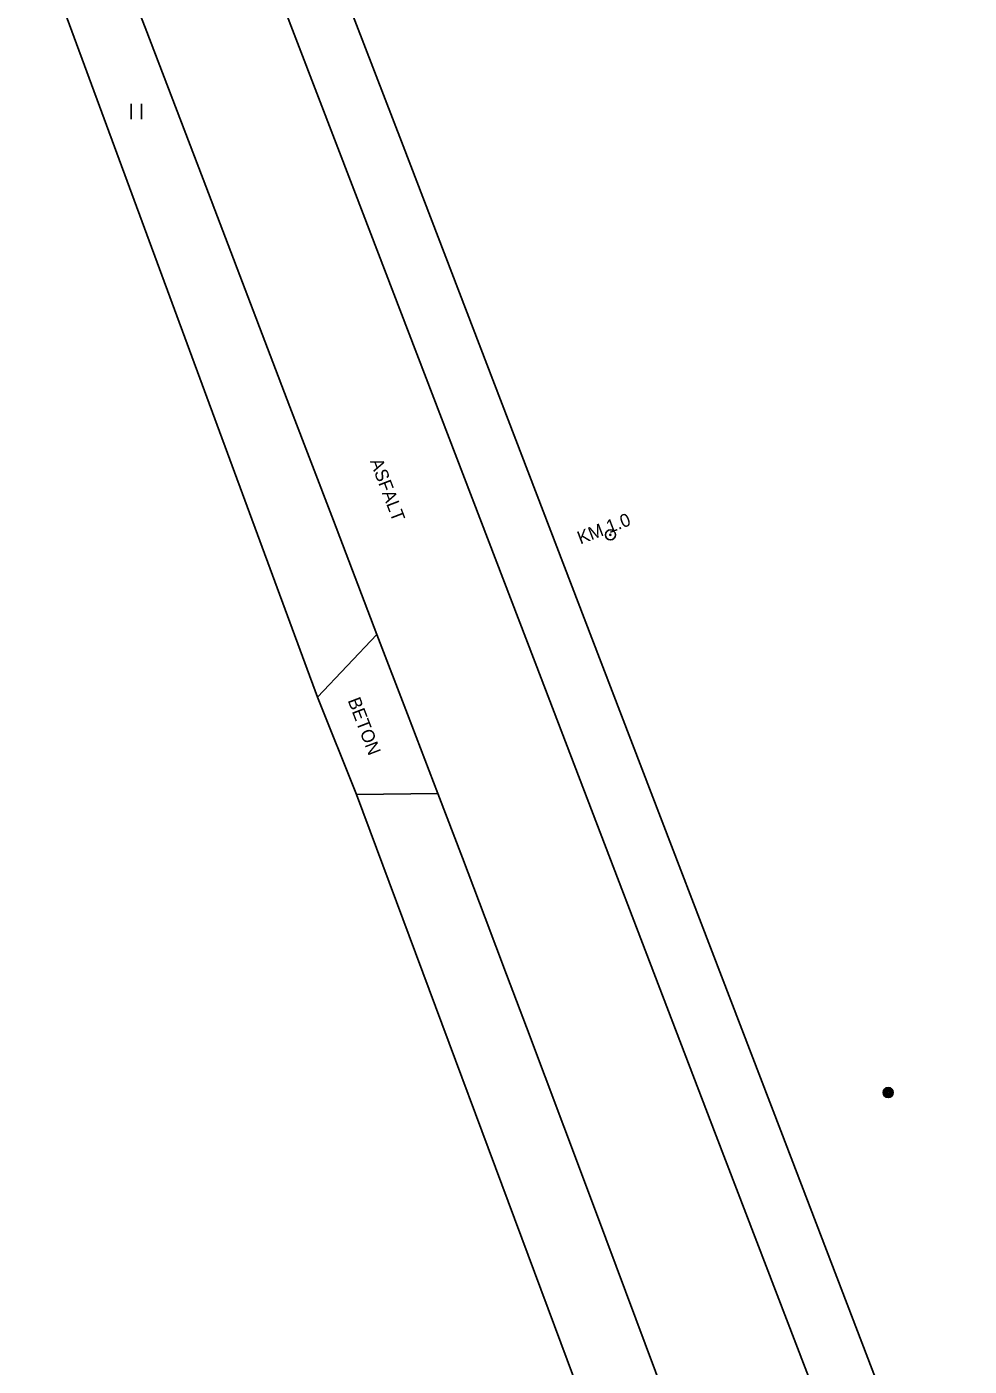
# Model space of a CAD drawing. Extents: x -539244 to -537359, y -1183785 to -1181851.
# Drawn here: x -538530 to -538483, y -1183558.8 to -1183492.1 of the extents above; entities that cross this region are included whole.
import ezdxf

# ---------------------------------------------------------------- set-up
doc = ezdxf.new("R2010")
doc.units = 0
for name, color, linetype in [('Vrstva 10', 7, 'Continuous'), ('Vrstva 11', 7, 'Continuous'), ('Vrstva 13', 7, 'Continuous'), ('Vrstva 25', 7, 'Continuous'), ('Vrstva 36', 7, 'Continuous'), ('Vrstva 40', 7, 'Continuous'), ('Vrstva 7', 7, 'Continuous'), ('Vrstva 8', 7, 'Continuous')]:
    doc.layers.add(name, color=color, linetype=linetype)

msp = doc.modelspace()

# ---------------------------------------------------------------- linework, layer by layer
at = {"layer": 'Vrstva 10'}
for p, q in [((-538522.069, -1183478.345), (-538513.7, -1183500.16)), ((-538525.756, -1183487.774), (-538524.101, -1183492.093)), ((-538524.101, -1183492.093), (-538521.21, -1183499.652)), ((-538521.21, -1183499.652), (-538516.877, -1183510.992)), ((-538513.7, -1183500.16), (-538504.66, -1183523.735)), ((-538516.877, -1183510.992), (-538514.71, -1183516.661)), ((-538514.71, -1183516.661), (-538512.54, -1183522.33)), ((-538504.66, -1183523.735), (-538495.62, -1183547.31)), ((-538506.079, -1183539.267), (-538505.084, -1183541.904)), ((-538505.084, -1183541.904), (-538503.223, -1183546.851)), ((-538503.223, -1183546.851), (-538501.598, -1183551.18)), ((-538495.62, -1183547.31), (-538483.01, -1183580.2)), ((-538501.598, -1183551.18), (-538495.924, -1183566.339))]:
    msp.add_line(p, q, dxfattribs=at)
for points in [[(-538512.54, -1183522.33), (-538511.019, -1183526.295), (-538509.5, -1183530.26)], [(-538509.5, -1183530.26), (-538508.282, -1183533.457), (-538507.144, -1183536.455), (-538506.079, -1183539.267)]]:
    msp.add_lwpolyline(points, dxfattribs=at)
at = {"layer": 'Vrstva 11'}
for p, q in [((-538515.5, -1183525.45), (-538512.54, -1183522.33)), ((-538509.5, -1183530.26), (-538513.56, -1183530.31))]:
    msp.add_line(p, q, dxfattribs=at)
at = {"layer": 'Vrstva 13'}
for p, q in [((-538511.24, -1183497.98), (-538519.435, -1183476.615)), ((-538501.825, -1183522.52), (-538511.24, -1183497.98)), ((-538492.41, -1183547.06), (-538501.825, -1183522.52)), ((-538486.178, -1183563.312), (-538492.41, -1183547.06))]:
    msp.add_line(p, q, dxfattribs=at)
at = {"layer": 'Vrstva 25'}
for centre, radius in [((-538500.9, -1183517.37), 0.25), ((-538500.9, -1183517.37), 0.0303), ((-538487.05, -1183545.16), 0.25), ((-538487.05, -1183545.16), 0.2), ((-538487.05, -1183545.16), 0.15), ((-538487.05, -1183545.16), 0.1), ((-538487.05, -1183545.16), 0.05)]:
    msp.add_circle(centre, radius, dxfattribs=at)
at = {"layer": 'Vrstva 36'}
for p, q in [((-538524.788, -1183496.649), (-538524.788, -1183495.899)), ((-538524.287, -1183496.649), (-538524.287, -1183495.899))]:
    msp.add_line(p, q, dxfattribs=at)
at = {"layer": 'Vrstva 7'}
for p, q in [((-538530, -1183486.17), (-538515.5, -1183525.45)), ((-538513.56, -1183530.31), (-538493.57, -1183583.86))]:
    msp.add_line(p, q, dxfattribs=at)
at = {"layer": 'Vrstva 8'}
msp.add_line((-538513.56, -1183530.31), (-538515.5, -1183525.45), dxfattribs=at)

# ---------------------------------------------------------------- texts
at = {"layer": 'Vrstva 40'}
for s, rotation, p in [('ASFALT', 290.92909, (-538512.898, -1183513.699)), ('KM 1.0', 20.9911, (-538502.399, -1183517.85)), ('BETON', 290.99882, (-538514.008, -1183525.615))]:
    msp.add_text(s, height=0.65, rotation=rotation, dxfattribs=at).set_placement(p)

doc.saveas('drawing.dxf')
